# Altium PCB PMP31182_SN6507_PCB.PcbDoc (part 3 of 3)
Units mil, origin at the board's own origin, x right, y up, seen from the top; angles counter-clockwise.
Board outline 4922 x 2266 mil, 4 copper layers (Top Layer, Signal Layer 1, Signal Layer 2, Bottom Layer), stack 77.9 mil thick; 174 components, 102 nets, 540 pads, 580 vias.
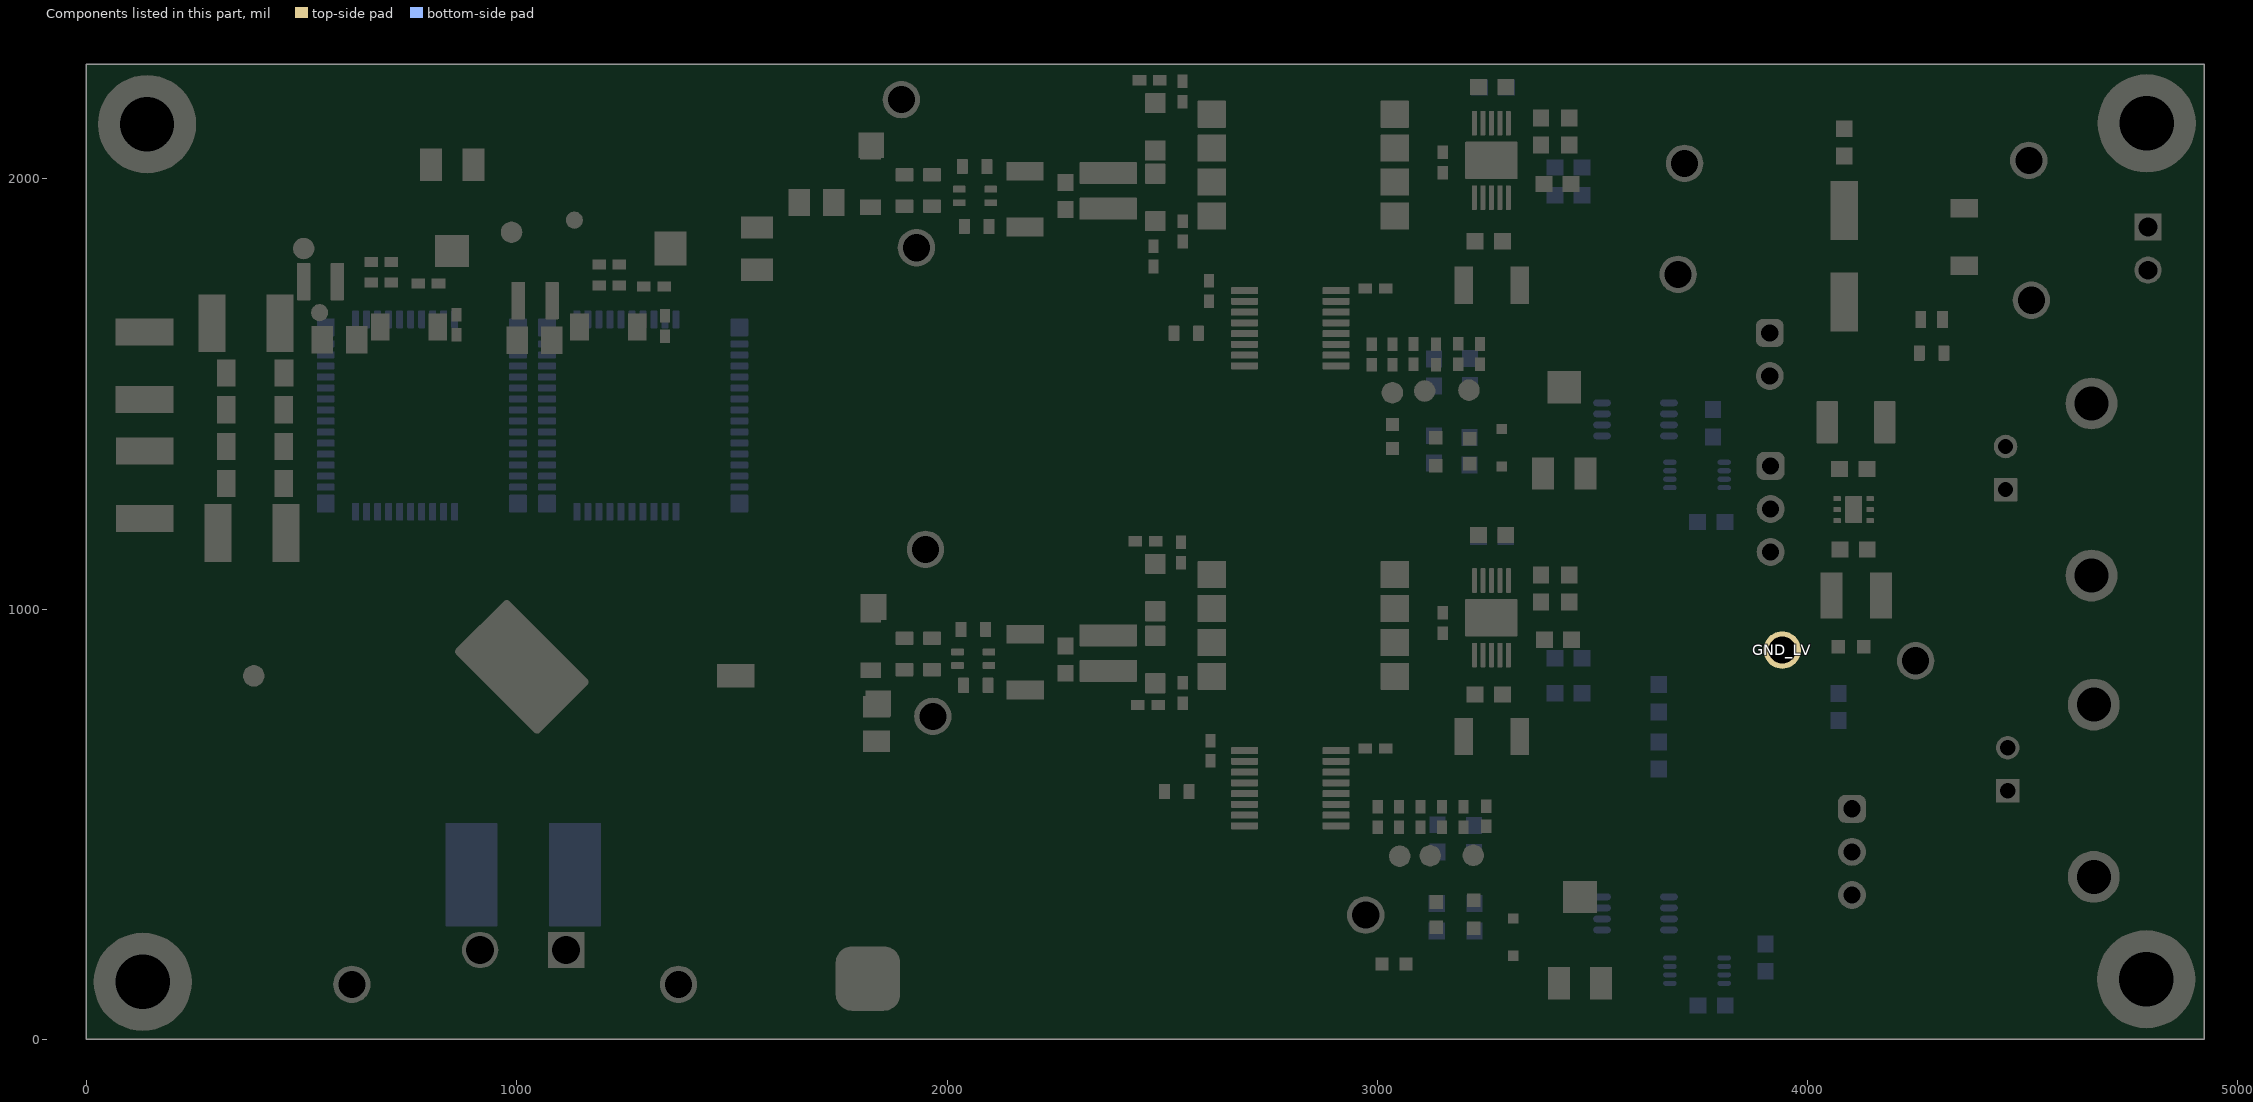
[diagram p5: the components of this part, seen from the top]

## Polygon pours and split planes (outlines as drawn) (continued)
GND_HV on Bottom Layer "GND_HV_L04_P016" (solid, remove dead copper, pour order 16): 900,1639 893,1646 786,1646 652,1646 580,1574 470,1574 450,1554 450,1154 470,1134 820,1134 900,1214
SW on Bottom Layer "SW_L04_P147" (solid, remove dead copper, pour order 147): 970.29,1674.3 970.29,1165.3 895,1090 895,1069 905,1059 1221,1059 1238.29,1076.29 1238.29,1175.29 1260.89,1197.89 1371,1198 1380,1207 1380,1246 1240,1386 1240,1450.84 1380,1590.84 1380,1636 1370,1646 1131,1646 1100,1615 1100,1583 1091,1574 1032,1574 1024,1582 1024,1673.77 1013.76,1684 980,1684
HVBUS on Bottom Layer "HVBUS_L04_P157" (solid, remove dead copper, pour order 157): 1540,1672.95 1540,1214 1470,1214 1450,1234 1450,1654 1473,1677 1535.95,1677
GND_LV on Signal Layer 2 "Signal Layer 1-GND_LV" (solid, pour order 182): 2934,1303.5 2941.5,1311 2987,1311 3008,1332 3008,1488 2977,1519 2977,1744 3091,1858 3091,2239 3583,2239 3787,2239 3833,2193 3832,2192 3832,1610 3868,1575 4770,1575 4859,1486 4859,416 4466,23 3172,23 3110,85 3110,270 3005,375 3005,442 2900,442 2898,440 2898,491 2996.53,491 3008,502.47 3008,670 3141,803 3141,1110 3008,1243 2945,1243 2934,1254
SW on Signal Layer 2 "SW_L03_P002" (solid, remove dead copper, pour order 2): 2407,1037 2566,1037 2586.56,1016.44 2586.56,757.44 2691,653 2713,631 2713,484 2700,471 2475.05,471 1607,1289.18 1607,1637.45 1530.46,1714 1474,1714 1354,1594 984,1594 973,1605 973,1865 1022,1914 1530,1914 1960,1484
HVBUS on Signal Layer 2 "HVBUS_L03_P054" (solid, remove dead copper, pour order 54): 376,22 317.88,64 317.88,192.12 79.88,430.12 79.88,1709.88 95,1725 342,1725 476,1591 476,1530 1406.59,1530 1491.2,1635.68 1531.32,1635.68 1538.88,1628.12 1538.88,1226.88 1525,1213 935,1213 758.88,1036.88 758.88,470.68 763.88,470.68 814.88,419.68 953.88,419.68 953.88,417.99 977.88,393.99 977.88,60 928,22
GND_HV on Signal Layer 2 "GND_HV_L03_P096" (solid, remove dead copper, pour order 96): 484,1655.47 484,2146 575,2237 2471,2237 2679,2029 2679,1579.01 2643.99,1544 2037,1544 1627,1954 957,1954 920,1917 920,1620 894,1594 545.48,1594
5V on Signal Layer 2 "5V_L03_P136" (solid, pour order 136): 4375.35,797.4 4114.35,797.4 4114.35,944.4 4118.35,948.4 4118.35,1110.4 4118.35,1156.4 4148.35,1186.4 4171.35,1186.4 4171.35,1223.4 4147.69,1247.06 4147.69,1251.4 4137.35,1251.4 4135.35,1253.4 4135.35,1263.4 4153.35,1263.4 4375.35,1263.4
GND_LV on Signal Layer 1 "Signal Layer 1-GND_LV" (solid, pour order 134): 2934,1296 2949,1311 2987,1311 3008,1332 3008,1488 2977,1519 2977,1744 3091,1858 3091,2239 3583,2239 3787,2239 3833,2193 3832,2192 3832,1610 3868,1575 4770,1575 4859,1486 4859,416 4466,23 3172,23 3110,85 3110,270 3005,375 3005,442 2900,442 2898,440 2898,491 2996.53,491 3008,502.47 3008,675 3143,810 3143,1118 3018,1243 2945,1243 2934,1254
GND_HV on Signal Layer 1 "GND_HV_L02_P008" (solid, remove dead copper, pour order 8): 1748,312 1748,313 1706,356 1706,1084 1606,1184 1450,1184 1420,1214 1420,1544 1390,1574 500,1574 481,1593 481,1763 470,1774 320,1774 310,1764 310,1674 283,1647 97,1647 70,1620 70,1064 90,1044 730,1044 888,1202 1251,1202 1300,1153 1300,561 1300.32,560.76 1300.32,560.32 1247,507 1099,507 1073,481 1073,50.87 1103.87,20 1922,20 1923,19 1955,51 1955,260 1903,312
SW on Top Layer "Top Layer-No Net" (solid, pour order 193): 1301,1685 1299,1687 1292.24,1687 1259,1687 cw(c1258.98,1695.8) 1250.18,1695.82 1250.18,1731.5 1257,1738 1308.8,1738 1311,1741 1311,1761.81 1306,1766 1226.81,1766 1223,1762.18 1223,1740 1233.18,1729.82 1233.17,1693.57 1233.17,1682.07 1223,1671.9 1185,1671.9 1177.05,1663.95 1176.73,1618.6 1172,1615.42 1110.58,1615.42 1106.12,1619.88 1106.11,1656.49 1098.12,1669.79 1098.12,1759.88 1096.19,1761.81 1068.81,1761.81 1067,1760 1067,1670.21 1056.12,1656.65 1056.12,1595.32 1069.33,1588.58 1351.95,1588.58 ccw(c1351.95,1596.8) 1360.18,1596.8 1360.18,1646.58 1356.28,1650 1313.22,1650 1301,1661
GND_HV on Top Layer "Top Layer-GND_HV" (solid, pour order 192): 924.5,2070 921.5,2073 877.5,2073 874.5,2070 874.5,1991 cw(c865.51,1990.99) 865.5,1982 763.37,1982 749.5,1968.13 749.5,1778.65 741.56,1770.72 701.5,1770.72 697.22,1770.72 693.5,1767 693.5,1740 704.5,1729 719.5,1714 719.5,1698 712.5,1691 712.5,1618 656,1618 653,1621 653,1655.5 651.5,1657 605,1657 603.5,1655.5 603.5,1599 608.5,1594 894.5,1594 900.5,1600 900.5,1644 890.5,1654 845.5,1654 840.5,1659 840.5,1686 749.5,1686 737.5,1698 737.5,1715.41 787.5,1745.19 787.5,1948 911.5,1948 ccw(c911.51,1960.99) 924.5,1961
15V_F on Top Layer "Top Layer-15V_F" (solid, pour order 105): 3338,597 3311,624 3311,743 3271,783 3271,819 3259,835 3259,920 3261,922 3269,922 3271,920 3271,848 3309,810 3309,789 3351,747 3352,748 3488,748 3622.73,882.73 3622.73,936.73 3624,938 3623,939 3623,1561 3575,1621 3369.25,1621 3310,1685.64 3310,1782 3285,1807 3283,1809 3280,1812 3270,1822 3270,1878.5 3259,1889.5 3259,1983 3261,1985 3269,1985 3271,1983 3271,1906 3310,1867 3310,1838 3343,1805 3633,1805 4268,1805 4275.44,1797.56 4275.44,1572.44 4264,1561 3988,1561 3939,1610 3850,1610 3818,1580 3817,1580 3817,648.99 3777.64,597
NetC60_2 on Top Layer "NETC60_2_L01_P191" (solid, pour order 191): 2473,1859 2483,1859 2504,1859 2515,1870 2555,1870 2559.75,1865.25 2559.75,1838.75 2549,1828 2473,1828 2469,1832 2469,1855
NetC58_2 on Top Layer "NETC58_2_L01_P190" (solid, pour order 190): 2480.78,788.81 2480.78,788.78 2475,783 2475,766 2483,758 2551,758 2559.75,766.75 2559.75,792.25 2555,797 2515,797 2506.81,788.81
NetC59_2 on Top Layer "NETC59_2_L01_P189" (solid, pour order 189): 2551.5,1140 2556.5,1145 2556.5,1167 2542.5,1181 2480,1181 2469,1170 2469,1150 2473,1146 2526.5,1146 2532.5,1140
NetC61_2 on Top Layer "NETC61_2_L01_P188" (solid, pour order 188): 2554,2211 2559,2216 2559,2238 2545,2252 2490,2252 2479,2241 2479,2220 2482,2217 2529,2217 2535,2211
GND_HV on Top Layer "GND_HV_L01_P030" (solid, remove dead copper, pour order 30): 70,1524 60,1514 60,1344 70,1334 201,1334 208,1341 208,1514 198,1524
HVBUS on Top Layer "HVBUS_L01_P032" (solid, remove dead copper, pour order 32): 60,455 60,1234 70,1244 250,1244 270,1264 270,1584 250,1604 70,1604 60,1614 60,1720 74,1734 340,1734 350,1724 350,1071 377,1044 700,1044 740.14,1003.86 740.14,559 793,508 935,508 959,484 959,59 921,21 363.89,21 315,69.89 315,200
GND_HV on Top Layer "GND_HV_L01_P082" (solid, remove dead copper, pour order 82): 418,1783 429,1794 471,1794 481,1784 481,1667 481,1593 550,1524 1309,1524 1391,1442 1391,1216 1446,1161 1629,1161 1705,1085 1705,356 1748,312 1903,312 1955,260 1955,51 1923,19 1922,20 1705,20 1104.63,20 1074,56.55 1074,482 1099,507 1247,507 1299,559 1300,561 1300,1184.41 1254.37,1230.04 916.04,1230.04 790,1104 418,1104
SW on Top Layer "SW_L01_P088" (solid, remove dead copper, pour order 88): 975,1170 810,1005 810,644 830,624 1210,624 1238.29,652.29 1238.29,1159.71 1228,1170
VNEG_L on Top Layer "VNEG_L_L01_P097" (solid, remove dead copper, pour order 97): 579,1594 586,1601 586,1615 575,1626 575,1674 567,1682 567,1698 554,1711 536,1711 500,1675 500,1600 506,1594
15V on Top Layer "15V_L01_P104" (solid, pour order 104): 4846,1821 4859,1807 4859,1576 4846,1563 4312,1563 4300,1575 4300,1812 4309,1821
GND_HV on Top Layer "GND_HV_L01_P112" (solid, pour order 112): 1794,2216.09 1822,2240 2463,2240 2463,2218 2432,2218 2407,2193 2407,2154.5 2394,2141.5 2144.5,2141.5 2048,2045 2048,1968 2016,1968 2016,1983 2005,1994 1893,1994 1880,2004 1880,2034 1869,2045 1812,2045 1794,2057.83
GND_LV on Top Layer "Top Layer-GND_LV" (solid, pour order 114): 3514,1979 3533,1960 3928,1960 3939.55,1971.55 3939.55,2063.55 3970,2094 4250,2094 4489,1855 4846,1855 4858,1867 4858,1956 4827.7,1986.3 4674,1986.3 4637.3,2023 4638,2023 4638,2222 4621.71,2238.29 3934.27,2237.73 3934,2238 3533,2238 3514,2219
5V on Top Layer "5V_L01_P118" (solid, pour order 118): 4345,1263 4375,1233 4376,1231 4376,822 4351,797 4136,797 4115,818 4115,944 4144,973 4144,1085 4119,1110 4119,1156 4149,1186 4172,1186 4172,1227.34 4148.34,1251 4138,1251 4136,1253 4136,1263
GND_LV on Top Layer "GND_LV_L01_P138" (solid, pour order 138): 3104,1708 3114,1718 3114,1759 3101,1772 3019,1772 3004,1757 3004,1730.97 2996.03,1723 2925,1723 2925,1708
GND_LV on Top Layer "GND_LV_L01_P139" (solid, pour order 139): 3117.25,639.25 3126,648 3126,695 3117.75,703.25 3019,703.25 3004,688.25 3004,662.22 2996.03,654.25 2925,654.25 2925,639.25
SW on Top Layer "SW_L01_P145" (solid, pour order 145): 1608.82,1556 1623.82,1571 1675.6,1571 2076.79,1169.81 2453.19,1169.81 2456,1167 2456,1148 2454,1146 2429.38,1146 2363.38,1080 2125.71,1080 2045,999 2045,940 2039,934 2039,897 2035,893 2014,893 2010,897 2010,917 1885,917 1880,922 1880,957 1869,968 1799,968 1788,979 1788,1116.59 1608.82,1289.18
NetC11_2 on Top Layer "NETC11_2_L01_P148" (solid, pour order 148): 1638,1914 1632,1920 1632,1994 1495,2131 715,2131 660,2076 660,1859 647,1845 597,1845 585,1857 585,2164 640,2219 1564,2219 1682,2101 1682,1920 1676,1914
GND_HV on Top Layer "GND_HV_L01_P150" (solid, pour order 150): 2641,2102 2648,2095 2648,1966 2644,1962 2545.17,1962 2542,1965.17 2542,2097 2547,2102
15V_F on Top Layer "15V_F_L01_P151" (solid, pour order 151): 3121,1994 3126,1999 3160,1999 3164,2003 3164,2026 3160,2030 3144,2030 3140,2026 3128,2026 3121,2033 3121,2101.5 3018,2101.5 3008,2091 3008,1973 3019,1962 3112,1962 3121,1971
ISO_15V_L on Top Layer "ISO_15V_L_L01_P152" (solid, pour order 152): 1778,1989 1775,1992 1718,1992 1713,1982 1713,1918 1838,1793 1973,1793 2054,1874 2054,1907 2046,1907 2045,1908 2045,1951 1778,1951
GND_LV on Top Layer "GND_LV_L01_P154" (solid, pour order 154): 3201,2078 3144,2078 3140,2074 3140,2051 3145,2046 3161,2046 3164,2049 3199,2049 3204,2044 3204,2010 3214,2000 3238,2000 3239,1999 3239,1898 3232,1891 3171.5,1891 3164.5,1884 3164.5,1842.5 3168,1839 3179,1839 3179,1712 3178,1711 3179,1710 3214,1710 3236,1688 3248,1688 3254,1694 3254,1780 3221,1780 3221,1836 3247,1836 3247,1876 3251,1880 3251,2000 3318.62,2000 3327,2008.96 3327,2050 3336,2059 3425,2059 3431,2053 3431,1980 3440,1971 3462,1971 3470,1979 3470,2056 3464,2062 3464,2087 3453,2098 3367,2098 3355,2086 3209,2086
NetT2_4 on Top Layer "NETT2_4_L01_P155" (solid, pour order 155): 3212,2119 3220,2111 3220,2103 3222,2101 3229,2101 3231,2103 3231,2156 3229,2158 3098,2158 3074,2182 3011,2182 3007,2178 3007,2121 3009,2119 3073,2119
NetT2_1 on Top Layer "NETT2_1_L01_P156" (solid, pour order 156): 3208.61,1945 3220,1956.39 3220,1983 3221,1985 3229.5,1985 3231,1983.5 3231,1929 3230,1928 3220,1928 3204,1912 3102,1912 3073,1883 3009,1883 3007,1885 3007,1943 3009,1945 3074,1945
NetD4_1 on Top Layer "NETD4_1_L01_P158" (solid, pour order 158): 2311,1995 2317,1989 2501,1989 2507,1995 2507,2085 2502,2090 2317,2090 2311,2084
ISO_15V_L_B on Top Layer "ISO_15V_L_B_L01_P159" (solid, pour order 159): 2444,1910 2439,1905 2297,1905 2259,1867 2092,1867 2087,1872 2087,1947 2092,1952 2112,1952 2116,1948 2116,1931 2138,1909 2247,1909 2256,1918 2256,1942 2262,1948 2289,1948 2303,1948 2314,1956 2441,1956 2444,1953
NetC61_1 on Top Layer "NETC61_1_L01_P160" (solid, pour order 160): 2572,2160 2582,2150 2582,2125 2587,2120 2643,2120 2648,2125 2648,2175 2637,2186 2565,2186 2556,2195 2507,2195 2502,2200 2465,2200 2460,2195 2460,2159 2466,2153 2507,2153 2514,2160
NetC60_1 on Top Layer "NETC60_1_L01_P161" (solid, pour order 161): 2577,1921 2582,1926 2582,1942 2585,1945 2646,1945 2649,1942 2649,1883 2586,1883 2583,1886 2515,1886 2508,1879 2467,1879 2461,1885 2461,1921 2465,1925 2504,1925 2508,1921 2557,1921
GND_HV on Top Layer "GND_HV_L01_P162" (solid, pour order 162): 2468,1807.22 2472.78,1812 2473,1812 2537,1812 2547,1802 2547,1762 2531,1746 2497,1746 2468,1775
ISO_RET_L_B on Top Layer "ISO_RET_L_B_L01_P163" (solid, pour order 163): 2286,1972 2293,1979 2293,2012 2266,2039 2134,2039 2127,2046 2085,2046 2080,2041 2080,1990 2087,1983 2087,1971 2089,1969 2114,1969 2116,1971 2116,1983 2124,1983 2138,1997 2233,1997 2258,1972
GND_LV on Top Layer "GND_LV_L01_P164" (solid, pour order 164): 3253,937 3251,935 3251,817 3248,814 3248,780 3242,774 3222,774 3222,718 3249,718 3255,712 3255,592 3250,587 3239,587 3165.5,660.5 3165.5,822 3172.5,829 3233,829 3240,836 3240,935 3238,937 3216,937 3203.98,949.02 3203.98,974.35 3200.89,975.89 3144.11,975.89 3140,980 3140,1003 3144,1007 3196,1007 3213,1024 3356,1024 3368,1036 3454,1036 3465,1025 3465,1000 3471,994 3471,917 3463,909 3441,909 3432,918 3432,991 3426,997 3337,997 3326.02,986.02 3326.02,944.84 3318.69,937
NetT1_4 on Top Layer "NETT1_4_L01_P167" (solid, pour order 167): 3228.98,1039 3231,1041.02 3231,1093 3229,1095 3090,1095 3073,1112 3011,1112 3007,1108 3007,1051 3009,1049 3210,1049 3220,1039
NetT1_1 on Top Layer "NETT1_1_L01_P168" (solid, pour order 168): 3208,875 3220,887 3220,919 3222,921 3226.25,921 3228.98,921 3231,918.98 3231,867 3209,845 3105,845 3073,813 3011,813 3009,815 3009,873 3011,875
NetC59_1 on Top Layer "NETC59_1_L01_P169" (solid, pour order 169): 2568,1093 2582,1079 2582,1054 2587,1049 2643,1049 2648,1054 2648,1104 2637,1115 2565,1115 2556,1124 2507,1124 2502,1129 2465,1129 2460,1124 2460,1088 2466,1082 2507,1082 2518,1093
SW on Top Layer "SW_L01_P170" (solid, pour order 170): 2639,1032 2646,1025 2646,896 2642,892 2543.17,892 2540,895.17 2540,1027 2545,1032
NetD1_1 on Top Layer "NETD1_1_L01_P171" (solid, pour order 171): 2309,921 2315,915 2499,915 2505,921 2505,1011 2500,1016 2315,1016 2309,1010
ISO_15V_H_B on Top Layer "ISO_15V_H_B_L01_P172" (solid, pour order 172): 2440,835 2435,830 2293,830 2255,792 2088,792 2083,797 2083,872 2088,877 2108,877 2112,873 2112,856 2134,834 2243,834 2252,843 2252,867 2258,873 2285,873 2299,873 2310,881 2437,881 2440,878
ISO_RET_H_B on Top Layer "ISO_RET_H_B_L01_P173" (solid, pour order 173): 2286,896 2293,903 2293,932.5 2262.5,963 2130.5,963 2123.5,970 2081.5,970 2076.5,965 2076.5,914 2083.5,907 2083.5,895 2085.5,893 2110.5,893 2112.5,895 2112.5,907 2120.5,907 2134.5,921 2233,921 2258,896
ISO_15V_H on Top Layer "ISO_15V_H_L01_P174" (solid, pour order 174): 2033,875 2039,869 2039,841 2051,829 2051,729 2022,700 1935,700 1893,742 1807,742 1799,750 1799,865.12 1805.72,875 2010,875
NetC58_1 on Top Layer "NETC58_1_L01_P175" (solid, pour order 175): 2576,851 2582,857 2582,873 2584,875 2645,875 2648,872 2648,813 2585,813 2515,813 2507,805 2466,805 2461,810 2461,846 2466,851 2507,851 2556,851
SW on Top Layer "SW_L01_P177" (solid, pour order 177): 2336,748 2354,766 2457,766 2459,768 2459,786.22 2456.61,788.61 2351.61,788.61 2305.61,788.61 2285,768 2285,728 2291,722 2327,722 2336,731
GND_LV on Top Layer "GND_LV_L01_P179" (solid, pour order 179): 3900,1492 3900,745 3994,651 4501,651 4534,702 4534,745 4534,1466 4501,1499 3905.25,1499
15V_F on Top Layer "15V_F_L01_P184" (solid, pour order 184): 3120,924 3125,929 3159,929 3163,933 3163,956 3159,960 3143,960 3139,956 3127,956 3120,963 3120,1031.5 3017,1031.5 3007,1021 3007,903 3018,892 3111,892 3120,901

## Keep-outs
Keep-Out Layer:
  lines w10: 2141.71,2266 4922,2266 4922,0 3006,0
  text ".Layer_Name" at 502,-792.77 h30

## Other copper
Signal Layer 1:
  pour cut-out: 267,1132.33 267,1164.5 244.91,1178 130.3,1178 111.84,1162.73 111.84,1135 133.17,1119 162.28,1119 247,1119
  pour cut-out: 266,1227.07 306,1227.07 316,1241 316,1578.62 302.49,1595.51 269.25,1595.51 257,1579.17 257,1526.56 257,1241.86
Signal Layer 2:
  pour cut-out: 536,1336 546,1346 546,1411.23 538.99,1420 481.25,1420 473,1409 473,1348.18 480.88,1336
  pour cut-out: 534,1125 546,1137 546,1202.23 537.39,1213 482.75,1213 472,1198.67 472,1140.73 482.18,1125
  pour cut-out: 534,1227 547,1240 547,1302.98 537.39,1315 482.75,1315 473,1302 473,1241.18 482.18,1227
  pour cut-out: 536,1443 547,1454 547,1516.98 538.99,1527 481.25,1527 472,1514.67 472,1456.73 480.88,1443
  pour cut-out: 108,1399 119,1388 200.75,1388 212,1397 212,1454.75 197,1466 124.73,1466 108,1455.18

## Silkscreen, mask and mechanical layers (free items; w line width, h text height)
Top Overlay:
  lines w10: 556,1866 556,1884 557,1885 ; 577,1885 557,1885 ; 623,1819 557,1885
  text "-" at 4727.87,1978 h150 r90
  text "+" at 4658,1621.45 h150
  text "PWM BOT" at 4349.33,1231 h60 r90
  text "PWM TOP" at 4352,477 h60 r90
  text "Load_GND" at 1694,242 h60
  text "Max DC Input:  / 520 V/25 A" at 804,44 h60
  text "PMP31182_SN6507Q1" at 3604,23 h60
Bottom Overlay:
  text "Max DC Input:  / 520 V/25 A" at 1371,45 h30
Top Paste:
  text ".Layer_Name" at 5093,3542.51 h30
Bottom Paste:
  text ".Layer_Name" at 5093,3542.51 h30
Top Solder:
  text ".Layer_Name" at 5093,3542.51 h30
Bottom Solder:
  text ".Layer_Name" at 5093,3542.51 h30
M1 Board Outline:
  the board outline again, w15
  text ".Layer_Name" at 502,-792.77 h30
M2 Board Dimensions:
  rectangle: -70,-219.27 55,-94.27
  rectangle: 50,-344.77 425,-219.77
  lines w7: -75,-94.77 -75,-344.77 925,-344.77 925,-94.77 ; -70,-219.27 930,-219.27 ; -70,-94.27 930,-94.27 ; 50,-344.77 50,-94.77 ; 175,-344.77 175,-94.77 ; 425,-344.77 425,-94.77 ; 675,-344.77 675,-94.77
  lines w10: -14.57,3 2986.43,3 ; 0,604 0,2266 4922,2266 4922,0 3624,0 3619,5
  text ".Layer_Name" at 502,-792.77 h30
M3 3D STEP Top:
  lines w10: 0,9 0,2266 4922,2266 4922,9 0,9
  text ".Layer_Name" at 502,-792.77 h30
M4 3D STEP Bottom:
  lines w10: 588.72,2260 583.69,2256.46 208.56,2256.46 0,2139.46 0,0 4922,0 4922,2266 2136.21,2266 2130.21,2260 ; 524,1188 1550,1188 1550,1730 524,1730 524,1188
M5 Assembly Top:
  lines w10: -367,-864.44 6233,-864.44 ; -367,-661.11 6235,-661.11 ; -367,-457.77 -367,-1067.77 3638,-1067.77 6235,-1067.77 6235,-457.77 -366.5,-457.77 -366.5,-1067.77 ; 2098,-1067.77 2098,-457.77 ; 3365,-661.11 3365,-457.77 ; 4205,-661.11 4205,-457.77 ; 4224.5,3267.5 5800,3267.5 ; 4827,-1074.27 4827,-871.44
  text "PCB VIEWED FROM TOP SIDE" at 4287.5,3745.33 h30
  text "IGNORE ->" at 4287.5,3542.51 h30
  text "PLOT NAME =" at 4287.5,3336.67 h30
  text "COMPONENTS MARKED 'DNP' SHOULD NOT BE POPULATED." at 1078.5,-252.77 h30
  text "ASSEMBLY VARIANT:" at 1078,-368.27 h30
  text ".VariantName" at 2114,-368.27 h30
  text "BOARD #:" at 2173,-589.94 h30
  text ".PRJ_Number" at 2718.5,-589.94 h30
  text "REV:" at 3563,-589.94 h30
  text ".PCB_Rev" at 3854.5,-589.94 h30
  text "SVN REV:" at 4401,-589.94 h30
  text ".VersionControl_RevNumber" at 4907,-589.94 h30
  text ".plot_File_Name" at 502,-998.61 h30
  text "GENERATED    :" at 2175,-998.61 h30
  text ".Print_Date" at 3044.5,-998.61 h30
  text ".Print_Time" at 3773.5,-998.61 h30
  text "TEXAS INSTRUMENTS" at 5038,-998.61 h30
M6 Assembly Bottom:
  lines w10: -367.5,-661.61 6234.5,-661.61 ; -365.5,-864.94 6234.5,-864.94 ; 1662.5,-661.61 1662.5,-458.27 ; 2502.5,-661.61 2502.5,-458.27 ; 3769.5,-1068.27 3769.5,-458.27 ; 4658.5,-1068.27 6234,-1068.27 6234,-458.27 -367.5,-458.27 -367.5,-1068.27 2229.5,-1068.27 6234.5,-1068.27 6234.5,-458.27 ; 5631.5,3260.5 5631.5,3463.33
  text ".VersionControl_RevNumber" at 5551.5,3744.83 h30
  text "TEXAS INSTRUMENTS" at 5420.5,3336.17 h30
  text "COMPONENTS MARKED 'DNP' SHOULD NOT BE POPULATED." at 6724,-256.27 h30
  text ".VariantName" at 5680,-372.27 h30
  text "ASSEMBLY VARIANT:" at 6719,-372.27 h30
  text "SVN REV:" at 1466.5,-590.44 h30
  text ".PCB_Rev" at 2013,-590.44 h30
  text "REV:" at 2304.5,-590.44 h30
  text ".PRJ_Number" at 3149,-590.44 h30
  text "BOARD #:" at 3694.5,-590.44 h30
  text "PCB VIEWED FROM BOTTOM SIDE" at 6171,-590.44 h30
  text "IGNORE ->" at 2472.85,-792.77 h30
  text ".Print_Time" at 2094,-999.11 h30
  text ".Print_Date" at 2823,-999.11 h30
  text "GENERATED    :" at 3692.5,-999.11 h30
  text ".plot_File_Name" at 5365.5,-999.11 h30
  text "PLOT NAME =" at 6171,-999.11 h30
M9 Title Sheet:
  drawing of 57 lines, arcs and shapes, not listed
  text "1" at 664.84,8102.23 h30
  text "2" at 3160.5,8102.23 h30
  text "3" at 5649.84,8102.23 h30
  text "4" at 8156.51,8102.23 h30
  text "5" at 10655.5,8102.23 h30
  text "6" at 13160.5,8102.23 h30
  text "A" at -491.5,6959.23 h30
  text "A" at 14308.5,6959.23 h30
  text "B" at -491.5,4579.23 h30
  text "B" at 14308.5,4579.23 h30
  text "1" at 5255.84,3137.5 h30
  text "C" at 14308.5,2204.23 h30
  text "PROJECT TITLE:" at 11268.5,343.23 h30
  text "LMG342xRx0" at 11318.5,209.9 h30
  text "DESIGNED FOR:" at 11268.5,42.23 h30
  text ".PRJ_Customer" at 11318.5,-97.77 h30
  text "D" at -491.5,-165.77 h30
  text "D" at 14308.5,-165.77 h30
  text "FILE NAME:" at 11268.5,-257.77 h30
  text ".PCB_File_Name_No_Path" at 11318.5,-377.77 h30
  text "Texas Instruments (TI) and/or its licensors do not warrant the accuracy or completeness of this specification" at 6299,-539.61 h30
  text "ENGINEER:" at 11268.5,-547.77 h30
  text "LAYOUT BY:" at 12773.5,-547.77 h30
  text "or any information contained therein. TI and/or its licensors do not warrant that this design will meet" at 6254.02,-652.28 h30
  text "Rui Gao" at 11318.5,-702.77 h30
  text "Rui Gao" at 12824,-702.77 h30
  text "the specifications, will be suitable for your application or fit for any particular purpose, or will operate in" at 6254.02,-764.94 h30
  text ".Layer_Name" at 502,-792.77 h30
  text "ALTIUM DESIGNER VERSION:" at 12773.5,-857.77 h30
  text "an implementation. TI and/or its licensors do not warrant that the design is production worthy. You should" at 6254.02,-877.61 h30
  text "completely validate and test your design implementation to confirm the system functionality for your application." at 6299,-990.27 h30
  text ".print_Scale" at 11318.5,-991.1 h30
  text ".Application_BuildNumber" at 12824,-991.1 h30
  text "2" at 3160.5,-1197.77 h30
  text "3" at 5649.84,-1197.77 h30
  text "4" at 8156.51,-1197.77 h30
  text "5" at 10655.5,-1197.77 h30
  text "6" at 13160.5,-1197.77 h30
M10 Fab Notes:
  drawing of 185 lines, arcs and shapes, not listed
  text "DESIGN INFORMATION" at 12306.02,5975.73 h30
  text "MIN. TRACK WIDTH:" at 11661.46,5795.73 h30
  text "6" at 12757.7,5795.73 h30
  text "MIL" at 12912.46,5795.73 h30
  text "MIN. CLEARANCE:" at 11661.46,5663.73 h30
  text "5.5" at 12697.7,5663.73 h30
  text "MIL" at 12912.46,5663.73 h30
  text "MIN. VIA PAD SIZE:" at 11661.46,5531.73 h30
  text "16" at 12727.71,5531.73 h30
  text "MIL" at 12912.46,5531.73 h30
  text "4 MIL" at 12356.46,5390.01 h30
  text "MINIMUM ANNULAR RING" at 11332.23,5385.73 h30
  text "PER" at 11532.23,5267.73 h30
  text "IPC-D-275 CLASS 2 LEVEL C" at 11752.23,5267.73 h30
  text "MIL, HOLES" at 13240.46,5155.44 h30
  text "+/-" at 12848,5154.73 h30
  text "+/-" at 13702,5154.73 h30
  text "REGISTRATION TOLERANCES:" at 11332.23,5149.73 h30
  text "METAL" at 12532,5149.73 h30
  text "MIL" at 14057.46,5149.73 h30
  text "MATERIAL:" at 11257.46,4940.27 h30
  text "FR-4 High Tg" at 12243.9,4799.93 h30
  text "FR-408" at 11678.46,4791.36 h30
  text "X" at 12090.46,4791.36 h30
  text "OTHER" at 13166.46,4791.36 h30
  text "X" at 11877.46,4636.36 h30
  text "78.7 MIL (2.0 mm) +/-10%" at 11998.56,4628.65 h30
  text "THICKNESS:" at 11332.23,4624.36 h30
  text "OTHER" at 13283.46,4624.36 h30
  text "TOLERANCE:" at 11332.23,4466.36 h30
  text "X" at 12171.54,4466.36 h30
  text "ANSI IPC-6012 TYPE 3 CLASS 2" at 12358.48,4466.36 h30
  text "OTHER +/-" at 12358.46,4310.36 h30
  text "BOW & TWIST:" at 11332.23,4153.36 h30
  text "X" at 12171.54,4153.36 h30
  text "ANSI IPC-6012 TYPE 3 CLASS 2" at 12358.48,4153.36 h30
  text "OTHER +/-" at 12358.46,3994.86 h30
  text "DRILLING:" at 11257.46,3856.36 h30
  text "REFERENCE:" at 11332.23,3739.36 h30
  text "X" at 11980.46,3739.36 h30
  text "AS SHOWN" at 12167.46,3739.36 h30
  text "X" at 12881.46,3739.36 h30
  text "NC_DRILL FILES" at 13018.46,3739.36 h30
  text "PTH MIN COPPER THICKNESS:" at 11332.23,3581.36 h30
  text "X" at 12674.46,3581.36 h30
  text "1MIL" at 12819.46,3581.36 h30
  text "OTHER" at 13316.46,3581.36 h30
  text "BOARD FINISH:" at 11257.46,3422.36 h30
  text "SILKSCREEN:" at 11412.68,3304.36 h30
  text "X" at 12361.46,3304.36 h30
  text "TOP" at 12487.46,3304.36 h30
  text "X" at 12871.46,3304.36 h30
  text "BOTTOM" at 12998.46,3304.36 h30
  text "SILKSCREEN COLOR:" at 11412.68,3137.36 h30
  text "X" at 12360.42,3137.36 h30
  text "WHITE" at 12487.46,3137.36 h30
  text "OTHER" at 12998.46,3137.36 h30
  text "SOLDER RESIST COLOR:" at 11412.68,2967.36 h30
  text "X" at 11980.42,2808.17 h30
  text "GREEN" at 12107.46,2808.17 h30
  text "BLUE" at 12698.46,2808.17 h30
  text "OTHER" at 13236.46,2808.17 h30
  text "IMMERSION GOLD (ENIG)" at 12318.46,2619.65 h30
  text "ENEPIG" at 13656,2616.36 h30
  text "SURFACE FINISH:" at 11257.46,2615.36 h30
  text "X" at 12131.51,2615.36 h30
  text "IMM. TIN/SILVER OR EQUIV" at 11587,2458.36 h30
  text "OTHER" at 13018.46,2458.36 h30
  text "X" at 12134,2287 h30
  text "ARRAY/PANEL:" at 11257.46,2279.36 h30
  text "CUT AND TRIM PER MECH LAYER 1" at 12318.46,2275.08 h30
  text "N.C. ROUTE" at 12318.46,2123.36 h30
  text "V. SCORE" at 13184.46,2123.36 h30
  text "CERTIFICATION:" at 11257.46,1986.36 h30
  text "MATERIALS AND WORKMANSHIP FOR ALL PCBS" at 11982.46,1986.36 h30
  text "TO MEET OR EXCEED THE REQUIREMENTS OF:" at 11982.46,1888.36 h30
  text "X" at 11608.96,1751.86 h30
  text "ANSI IPC-A-600F CLASS ->" at 11747.96,1751.86 h30
  text "X" at 13387.02,1751.86 h30
  text "2" at 13505.96,1751.86 h30
  text "1" at 13190.96,1750.36 h30
  text "3" at 13859.96,1750.36 h30
  text "X" at 11611.02,1592.36 h30
  text "UL 94V-0" at 11747.96,1592.36 h30
  text "X" at 12423.02,1592.36 h30
  text "RoHS" at 12559.96,1592.36 h30
  text "OTHER" at 13204.37,1592.36 h30
  text "PER ORDER" at 13601.42,1592.36 h30
  text "ADDITIONAL REQUIREMENTS:" at 11257.46,1451.36 h30
  text "MICROSECTION:" at 11332.23,1336.36 h30
  text "YES" at 12237.96,1336.36 h30
  text "REQUIRED" at 13099.46,1180.22 h30
  text "BARE BOARD ELEC. TEST:" at 11332.23,1177.36 h30
  text "NONE" at 12637.96,1177.36 h30
  text "X" at 12972.46,1177.36 h30
  text "PER ORDER" at 13691.46,1177.36 h30
  text "MANUFACTURER'S UL:" at 11332.23,1020.36 h30
  text "RAIL" at 12497.96,1016.08 h30
  text "METAL" at 12989.78,1016.08 h30
  text "X" at 13365,1015.73 h30
  text "SILK" at 13501.46,1016.08 h30
  text ".Layer_Name" at 502,-792.77 h30
M11 Gerber Information:
  lines w10: -367,-864.44 6233,-864.44 ; -367,-661.11 6235,-661.11 ; -367,-457.77 -367,-1067.77 3638,-1067.77 6235,-1067.77 6235,-457.77 -366.5,-457.77 -366.5,-1067.77 ; 2098,-1067.77 2098,-457.77 ; 3365,-661.11 3365,-457.77 ; 4205,-661.11 4205,-457.77 ; 4224.5,3267.5 5800,3267.5 ; 4827,-1074.27 4827,-871.44
  text "PLOT NAME =" at 4287.5,3336.67 h30
  text "BOARD #:" at 2173,-589.94 h30
  text ".PRJ_Number" at 2718.5,-589.94 h30
  text "REV:" at 3563,-589.94 h30
  text ".PCB_Rev" at 3854.5,-589.94 h30
  text "SVN REV:" at 4401,-589.94 h30
  text ".VersionControl_RevNumber" at 4907,-589.94 h30
  text ".plot_File_Name" at 502,-998.61 h30
  text "GENERATED    :" at 2175,-998.61 h30
  text ".Print_Date" at 3044.5,-998.61 h30
  text ".Print_Time" at 3773.5,-998.61 h30
  text "TEXAS INSTRUMENTS" at 5038,-998.61 h30
M12 Stackup:
  drawing of 295 lines, arcs and shapes, not listed
  text "Layer" at 9552.84,7738.23 h60
  text "Name" at 9962.76,7738.23 h60
  text "Material" at 10902.5,7738.23 h60
  text "Thickness" at 11762.26,7738.23 h60
  text "Constant" at 12412.1,7738.23 h60
  text "Board Layer Stack" at 12981.96,7738.23 h60
  text "Top Overlay" at 9962.76,7618.23 h60
  text "Top Solder" at 9962.76,7498.23 h60
  text "Solder Resist" at 10902.5,7498.23 h60
  text "0.40mil" at 11762.26,7498.23 h60
  text "3.5" at 12412.1,7498.23 h60
  text "1" at 9552.84,7378.23 h60
  text "Top Layer" at 9962.76,7378.23 h60
  text "2.80mil" at 11762.26,7378.23 h60
  text "Dielectric 1" at 9962.76,7258.23 h60
  text "FR-4" at 10902.5,7258.23 h60
  text "4.60mil" at 11762.26,7258.23 h60
  text "4.2" at 12412.1,7258.23 h60
  text "2" at 9552.84,7138.23 h60
  text "Signal Layer 1" at 9962.76,7138.23 h60
  text "2.80mil" at 11762.26,7138.23 h60
  text "Dielectric 2" at 9962.76,7018.23 h60
  text "FR-4" at 10902.5,7018.23 h60
  text "57.50mil" at 11762.26,7018.23 h60
  text "4.2" at 12412.1,7018.23 h60
  text "3" at 9552.84,6898.23 h60
  text "Signal Layer 2" at 9962.76,6898.23 h60
  text "2.80mil" at 11762.26,6898.23 h60
  text "Dielectric 3" at 9962.76,6778.23 h60
  text "FR-4" at 10902.5,6778.23 h60
  text "4.60mil" at 11762.26,6778.23 h60
  text "4.2" at 12412.1,6778.23 h60
  text "4" at 9552.84,6658.23 h60
  text "Bottom Layer" at 9962.76,6658.23 h60
  text "2.80mil" at 11762.26,6658.23 h60
  text "Bottom Solder" at 9962.76,6538.23 h60
  text "Solder Resist" at 10902.5,6538.23 h60
  text "0.40mil" at 11762.26,6538.23 h60
  text "3.5" at 12412.1,6538.23 h60
  text "Bottom Overlay" at 9962.76,6418.23 h60
  text ".Layer_Name" at 5093,3542.51 h30
M13 Component Bodies Top:
  text ".Layer_Name" at 502,-792.77 h30
M14 Component Bodies Bottom:
  text ".Layer_Name" at 502,-792.77 h30
M15 Courtyards Top:
  text ".Layer_Name" at 502,-792.77 h30
M16 Courtyards Bottom:
  text ".Layer_Name" at 502,-792.77 h30
Drill Drawing:
  circle w10: c6502.89,409.18 r23.04
  lines w10: 6479.85,86.62 6491.37,86.62 6502.89,75.1 6514.41,86.62 6525.93,86.62 6514.41,98.14 6525.93,109.66 6514.41,109.66 6502.89,121.18 6491.37,109.66 6479.85,109.66 6491.37,98.14 6479.85,86.62 ; 6479.85,178.78 6479.85,190.3 6491.37,201.82 6479.85,213.34 6479.85,224.86 6491.37,224.86 6502.89,213.34 6514.41,224.86 6525.93,224.86 6525.93,213.34 6514.41,201.82 6525.93,190.3 6525.93,178.78 6514.41,178.78 6502.89,190.3 6491.37,178.78 6479.85,178.78 ; 6479.85,282.46 6525.93,282.46 6525.93,328.54 6479.85,328.54 6479.85,282.46 ; 6479.85,639.59 6525.93,639.59 6502.89,593.51 6479.85,639.59 ; 6479.85,708.71 6491.37,708.71 6491.37,697.19 6514.41,697.19 6514.41,708.71 6525.93,708.71 6525.93,731.75 6514.41,731.75 6514.41,743.27 6491.37,743.27 6491.37,731.75 6479.85,731.75 6479.85,708.71 ; 6479.85,812.39 6491.37,812.39 6491.37,800.87 6514.41,800.87 6514.41,812.39 6525.93,812.39 6525.93,835.43 6514.41,835.43 6514.41,846.95 6491.37,846.95 6491.37,835.43 6479.85,835.43 6479.85,812.39 ; 6479.85,904.55 6479.85,916.07 6491.37,927.59 6479.85,939.11 6479.85,950.63 6491.37,950.63 6502.89,939.11 6514.41,950.63 6525.93,950.63 6525.93,939.11 6514.41,927.59 6525.93,916.07 6525.93,904.55 6514.41,904.55 6502.89,916.07 6491.37,904.55 6479.85,904.55 ; 6479.85,1019.75 6491.37,1019.75 6502.89,1008.23 6514.41,1019.75 6525.93,1019.75 6514.41,1031.27 6525.93,1042.79 6514.41,1042.79 6502.89,1054.31 6491.37,1042.79 6479.85,1042.79 6491.37,1031.27 6479.85,1019.75 ; 6489.06,188 6489.06,194.91 6495.98,201.82 6489.06,208.73 6489.06,215.65 6495.98,215.65 6502.89,208.73 6509.8,215.65 6516.71,215.65 6516.71,208.73 6509.8,201.82 6516.71,194.91 6516.71,188 6509.8,188 6502.89,194.91 6495.98,188 6489.06,188 ; 6489.06,291.68 6516.71,291.68 6516.71,319.33 6489.06,319.33 6489.06,291.68 ; 6489.06,713.32 6495.98,713.32 6495.98,706.4 6509.8,706.4 6509.8,713.32 6516.71,713.32 6516.71,727.14 6509.8,727.14 6509.8,734.05 6495.98,734.05 6495.98,727.14 6489.06,727.14 6489.06,713.32 ; 6489.06,1024.36 6495.98,1024.36 6502.89,1017.45 6509.8,1024.36 6516.71,1024.36 6509.8,1031.27 6516.71,1038.18 6509.8,1038.18 6502.89,1045.1 6495.98,1038.18 6489.06,1038.18 6495.98,1031.27 6489.06,1024.36
  lines w12: 6437.55,44 10686.45,44 ; 6437.55,1080.81 10686.45,1080.81 ; 6828.21,-59.68 6828.21,1184.49 ; 7278.96,-59.68 7278.96,1184.49 ; 8218.94,-59.68 8218.94,1184.49 ; 8578.48,-59.68 8578.48,1184.49 ; 9095.57,-59.68 9095.57,1184.49 ; 10138.25,-59.68 10138.25,1184.49 ; 6437.55,-59.68 10686.45,-59.68 10686.45,1184.49 6437.55,1184.49 6437.55,-59.68
  text ".Layer_Name" at 5093,3542.51 h30
  text "Symbol" at 6499.76,1111.91 h49.77
  text "Quantity" at 6859.31,1111.91 h49.77
  text "Finished Hole Size" at 7310.07,1111.91 h49.77
  text "Plated" at 8250.04,1111.91 h49.77
  text "Hole Type" at 8609.59,1111.91 h49.77
  text "Drill Layer Pair" at 9126.68,1111.91 h49.77
  text "Tolerance" at 10169.36,1111.91 h49.77
  text "14" at 6859.31,1008.23 h41.47
  text "7.87mil (0.200mm)" at 7310.07,1008.23 h41.47
  text "PTH" at 8250.04,1008.23 h41.47
  text "Round" at 8609.59,1008.23 h41.47
  text "Top Layer - Bottom Layer" at 9126.68,1008.23 h41.47
  text "562" at 6859.31,904.55 h41.47
  text "10.00mil (0.254mm)" at 7310.07,904.55 h41.47
  text "PTH" at 8250.04,904.55 h41.47
  text "Round" at 8609.59,904.55 h41.47
  text "Top Layer - Bottom Layer" at 9126.68,904.55 h41.47
  text "4" at 6859.31,800.87 h41.47
  text "31.50mil (0.800mm)" at 7310.07,800.87 h41.47
  text "PTH" at 8250.04,800.87 h41.47
  text "Round" at 8609.59,800.87 h41.47
  text "Top Layer - Bottom Layer" at 9126.68,800.87 h41.47
  text "4" at 6859.31,697.19 h41.47
  text "35.04mil (0.890mm)" at 7310.07,697.19 h41.47
  text "PTH" at 8250.04,697.19 h41.47
  text "Round" at 8609.59,697.19 h41.47
  text "Top Layer - Bottom Layer" at 9126.68,697.19 h41.47
  text "8" at 6859.31,593.51 h41.47
  text "40.00mil (1.016mm)" at 7310.07,593.51 h41.47
  text "PTH" at 8250.04,593.51 h41.47
  text "Round" at 8609.59,593.51 h41.47
  text "Top Layer - Bottom Layer" at 9126.68,593.51 h41.47
  text "2" at 6859.31,489.83 h41.47
  text "43.31mil (1.100mm)" at 7310.07,489.83 h41.47
  text "PTH" at 8250.04,489.83 h41.47
  text "Round" at 8609.59,489.83 h41.47
  text "Top Layer - Bottom Layer" at 9126.68,489.83 h41.47
  text "A" at 6477.53,479.83 h46.08
  text "13" at 6859.31,386.14 h41.47
  text "63.00mil (1.600mm)" at 7310.07,386.14 h41.47
  text "PTH" at 8250.04,386.14 h41.47
  text "Round" at 8609.59,386.14 h41.47
  text "Top Layer - Bottom Layer" at 9126.68,386.14 h41.47
  text "2" at 6859.31,282.46 h41.47
  text "64.96mil (1.650mm)" at 7310.07,282.46 h41.47
  text "PTH" at 8250.04,282.46 h41.47
  text "Round" at 8609.59,282.46 h41.47
  text "Top Layer - Bottom Layer" at 9126.68,282.46 h41.47
  text "4" at 6859.31,178.78 h41.47
  text "79.13mil (2.010mm)" at 7310.07,178.78 h41.47
  text "PTH" at 8250.04,178.78 h41.47
  text "Round" at 8609.59,178.78 h41.47
  text "Top Layer - Bottom Layer" at 9126.68,178.78 h41.47
  text "4" at 6859.31,75.1 h41.47
  text "125.98mil (3.200mm)" at 7310.07,75.1 h41.47
  text "PTH" at 8250.04,75.1 h41.47
  text "Round" at 8609.59,75.1 h41.47
  text "Top Layer - Bottom Layer" at 9126.68,75.1 h41.47
  text "617 Total" at 6859.31,-28.58 h41.47
Bottom Courtyard:
  pour cut-out: 536,1443 544,1451 544,1520.73 538.99,1527 481.25,1527 475,1518.67 475,1452.09 480.88,1443

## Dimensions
0,2266 to 0,0 on M2 Board Dimensions
-75,-344.77 to 925,-344.77 on M2 Board Dimensions
0,0 to 4922,0 on M2 Board Dimensions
